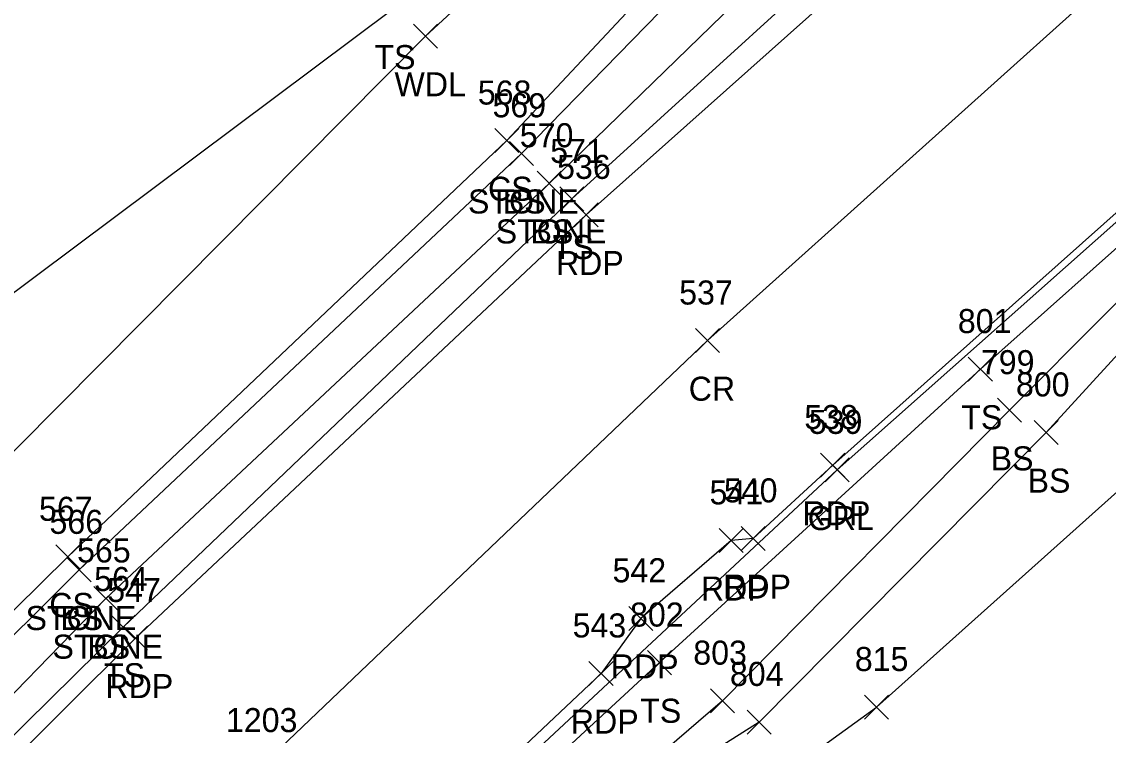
# Model space of a CAD drawing. Extents: x 1528286 to 1556263, y 492387 to 508952.
# Drawn here: x 1528382.4 to 1528472.8, y 492580.9 to 492640.2 of the extents above; entities that cross this region are included whole.
import ezdxf

# ---------------------------------------------------------------- set-up
doc = ezdxf.new("R2010")
doc.units = 0
for name, color, linetype in [('L_A', 7, 'Continuous'), ('L_I', 7, 'Continuous'), ('L_TIC', 7, 'Continuous'), ('LASF', 7, 'Continuous'), ('LAWA', 7, 'Continuous'), ('LELB', 7, 'Continuous'), ('P_A', 7, 'Continuous'), ('P_I', 7, 'Continuous'), ('P_TIC', 7, 'Continuous'), ('PET', 7, 'Continuous'), ('PRC', 7, 'Continuous'), ('R_A', 7, 'Continuous'), ('R_I', 7, 'Continuous'), ('R_TIC', 7, 'Continuous'), ('RGR', 7, 'Continuous')]:
    doc.layers.add(name, color=color, linetype=linetype)

msp = doc.modelspace()

# ---------------------------------------------------------------- linework, layer by layer
at = {"layer": 'L_TIC'}
for points in [[(1528415.012, 492638), (1528417.012, 492640)], [(1528417.012, 492638), (1528415.012, 492640)], [(1528415.012, 492638), (1528417.012, 492640)], [(1528417.012, 492638), (1528415.012, 492640)], [(1528421.772, 492629.308), (1528423.772, 492631.308)], [(1528423.772, 492629.308), (1528421.772, 492631.308)], [(1528421.772, 492629.308), (1528423.772, 492631.308)], [(1528423.772, 492629.308), (1528421.772, 492631.308)], [(1528423.002, 492628.248), (1528425.002, 492630.248)], [(1528425.002, 492628.248), (1528423.002, 492630.248)], [(1528423.002, 492628.248), (1528425.002, 492630.248)], [(1528425.002, 492628.248), (1528423.002, 492630.248)], [(1528423.002, 492628.248), (1528425.002, 492630.248)], [(1528425.002, 492628.248), (1528423.002, 492630.248)], [(1528423.002, 492628.248), (1528425.002, 492630.248)], [(1528425.002, 492628.248), (1528423.002, 492630.248)], [(1528425.307, 492625.756), (1528427.307, 492627.756)], [(1528427.307, 492625.756), (1528425.307, 492627.756)], [(1528425.307, 492625.756), (1528427.307, 492627.756)], [(1528427.307, 492625.756), (1528425.307, 492627.756)], [(1528425.307, 492625.756), (1528427.307, 492627.756)], [(1528427.307, 492625.756), (1528425.307, 492627.756)], [(1528425.307, 492625.756), (1528427.307, 492627.756)], [(1528427.307, 492625.756), (1528425.307, 492627.756)], [(1528427.184, 492624.456), (1528429.184, 492626.456)], [(1528429.184, 492624.456), (1528427.184, 492626.456)], [(1528427.184, 492624.456), (1528429.184, 492626.456)], [(1528429.184, 492624.456), (1528427.184, 492626.456)], [(1528461.188, 492610.303), (1528463.188, 492612.303)], [(1528463.188, 492610.303), (1528461.188, 492612.303)], [(1528461.188, 492610.303), (1528463.188, 492612.303)], [(1528463.188, 492610.303), (1528461.188, 492612.303)], [(1528463.603, 492606.884), (1528465.603, 492608.884)], [(1528465.603, 492606.884), (1528463.603, 492608.884)], [(1528463.603, 492606.884), (1528465.603, 492608.884)], [(1528465.603, 492606.884), (1528463.603, 492608.884)], [(1528466.677, 492605.034), (1528468.677, 492607.034)], [(1528468.677, 492605.034), (1528466.677, 492607.034)], [(1528466.677, 492605.034), (1528468.677, 492607.034)], [(1528468.677, 492605.034), (1528466.677, 492607.034)], [(1528385.249, 492594.69), (1528387.249, 492596.69)], [(1528387.249, 492594.69), (1528385.249, 492596.69)], [(1528385.249, 492594.69), (1528387.249, 492596.69)], [(1528387.249, 492594.69), (1528385.249, 492596.69)], [(1528386.178, 492593.605), (1528388.178, 492595.605)], [(1528388.178, 492593.605), (1528386.178, 492595.605)], [(1528386.178, 492593.605), (1528388.178, 492595.605)], [(1528388.178, 492593.605), (1528386.178, 492595.605)], [(1528386.178, 492593.605), (1528388.178, 492595.605)], [(1528388.178, 492593.605), (1528386.178, 492595.605)], [(1528386.178, 492593.605), (1528388.178, 492595.605)], [(1528388.178, 492593.605), (1528386.178, 492595.605)], [(1528388.417, 492591.224), (1528390.417, 492593.224)], [(1528390.417, 492591.224), (1528388.417, 492593.224)], [(1528388.417, 492591.224), (1528390.417, 492593.224)], [(1528390.417, 492591.224), (1528388.417, 492593.224)], [(1528388.417, 492591.224), (1528390.417, 492593.224)], [(1528390.417, 492591.224), (1528388.417, 492593.224)], [(1528388.417, 492591.224), (1528390.417, 492593.224)], [(1528390.417, 492591.224), (1528388.417, 492593.224)], [(1528389.84, 492588.848), (1528391.84, 492590.848)], [(1528391.84, 492588.848), (1528389.84, 492590.848)], [(1528389.84, 492588.848), (1528391.84, 492590.848)], [(1528391.84, 492588.848), (1528389.84, 492590.848)], [(1528434.473, 492585.893), (1528436.473, 492587.893)], [(1528436.473, 492585.893), (1528434.473, 492587.893)], [(1528434.473, 492585.893), (1528436.473, 492587.893)], [(1528436.473, 492585.893), (1528434.473, 492587.893)], [(1528439.739, 492582.726), (1528441.739, 492584.726)], [(1528441.739, 492582.726), (1528439.739, 492584.726)], [(1528439.739, 492582.726), (1528441.739, 492584.726)], [(1528441.739, 492582.726), (1528439.739, 492584.726)], [(1528452.537, 492582.197), (1528454.537, 492584.197)], [(1528454.537, 492582.197), (1528452.537, 492584.197)], [(1528452.537, 492582.197), (1528454.537, 492584.197)], [(1528454.537, 492582.197), (1528452.537, 492584.197)], [(1528452.537, 492582.197), (1528454.537, 492584.197)], [(1528454.537, 492582.197), (1528452.537, 492584.197)], [(1528452.537, 492582.197), (1528454.537, 492584.197)], [(1528454.537, 492582.197), (1528452.537, 492584.197)], [(1528442.787, 492580.956), (1528444.787, 492582.956)], [(1528444.787, 492580.956), (1528442.787, 492582.956)], [(1528442.787, 492580.956), (1528444.787, 492582.956)], [(1528444.787, 492580.956), (1528442.787, 492582.956)]]:
    msp.add_lwpolyline(points, dxfattribs=at)
at = {"layer": 'LASF'}
for points in [[(1528311.932, 492522.674), (1528350.128, 492557.714), (1528387.178, 492594.605), (1528424.002, 492629.248), (1528451.685, 492657.606), (1528445.371, 492665.36)], [(1528311.932, 492522.674), (1528350.128, 492557.714), (1528387.178, 492594.605), (1528424.002, 492629.248), (1528451.685, 492657.606), (1528445.371, 492665.36)], [(1528316.792, 492519.202), (1528352.681, 492554.477), (1528389.417, 492592.224), (1528426.307, 492626.756), (1528455.193, 492654.803), (1528460.128, 492658.522), (1528463.915, 492659.117), (1528453.913, 492663.497)], [(1528316.792, 492519.202), (1528352.681, 492554.477), (1528389.417, 492592.224), (1528426.307, 492626.756), (1528455.193, 492654.803), (1528460.128, 492658.522), (1528463.915, 492659.117), (1528453.913, 492663.497)]]:
    msp.add_lwpolyline(points, dxfattribs=at)
at = {"layer": 'LAWA'}
for points in [[(1528305.143, 492527.842), (1528342.933, 492565.336), (1528378.694, 492601.441), (1528416.012, 492639), (1528453.009, 492673.153), (1528472.803, 492690.435), (1528460.273, 492718.435)], [(1528305.143, 492527.842), (1528342.933, 492565.336), (1528378.694, 492601.441), (1528416.012, 492639), (1528453.009, 492673.153), (1528472.803, 492690.435), (1528460.273, 492718.435)], [(1528350.567, 492486.658), (1528374.131, 492513.994), (1528413.925, 492550.925), (1528435.091, 492569.848), (1528453.537, 492583.197), (1528487.048, 492613.162), (1528503.178, 492626.813), (1528522.579, 492648.478), (1528559.072, 492677.555), (1528579.271, 492695.125), (1528598.445, 492712.961), (1528609.007, 492715.026)], [(1528350.567, 492486.658), (1528374.131, 492513.994), (1528413.925, 492550.925), (1528435.091, 492569.848), (1528453.537, 492583.197), (1528487.048, 492613.162), (1528503.178, 492626.813), (1528522.579, 492648.478), (1528559.072, 492677.555), (1528579.271, 492695.125), (1528598.445, 492712.961), (1528609.007, 492715.026)]]:
    msp.add_lwpolyline(points, dxfattribs=at)
at = {"layer": 'LELB'}
for points in [[(1528627.535, 492747.197), (1528602.245, 492728.24), (1528590.919, 492720.18), (1528561.7, 492697.236), (1528528.44, 492669.894), (1528504.886, 492649.176), (1528486.55, 492633.133), (1528477.153, 492624.603), (1528462.188, 492611.303), (1528435.473, 492586.893), (1528420.499, 492573.078), (1528389.262, 492542.582), (1528363.671, 492517.292), (1528340.83, 492494.601)], [(1528627.535, 492747.197), (1528602.245, 492728.24), (1528590.919, 492720.18), (1528561.7, 492697.236), (1528528.44, 492669.894), (1528504.886, 492649.176), (1528486.55, 492633.133), (1528477.153, 492624.603), (1528462.188, 492611.303), (1528435.473, 492586.893), (1528420.499, 492573.078), (1528389.262, 492542.582), (1528363.671, 492517.292), (1528340.83, 492494.601)], [(1528318.253, 492517.35), (1528354.27, 492553.82), (1528390.84, 492589.848), (1528428.184, 492625.456), (1528458.023, 492652.609), (1528463.915, 492659.117), (1528457.385, 492666.329)], [(1528318.253, 492517.35), (1528354.27, 492553.82), (1528390.84, 492589.848), (1528428.184, 492625.456), (1528458.023, 492652.609), (1528463.915, 492659.117), (1528457.385, 492666.329)], [(1528311.932, 492522.674), (1528350.128, 492557.714), (1528387.178, 492594.605), (1528424.002, 492629.248), (1528451.685, 492657.606), (1528445.371, 492665.36)], [(1528311.932, 492522.674), (1528350.128, 492557.714), (1528387.178, 492594.605), (1528424.002, 492629.248), (1528451.685, 492657.606), (1528445.371, 492665.36)], [(1528441.343, 492661.958), (1528423.93, 492647.619), (1528413.351, 492641.257), (1528373.584, 492611.591), (1528326.921, 492585.971), (1528288.158, 492548.496)], [(1528441.343, 492661.958), (1528423.93, 492647.619), (1528413.351, 492641.257), (1528373.584, 492611.591), (1528326.921, 492585.971), (1528288.158, 492548.496)], [(1528310.29, 492523.886), (1528348.881, 492558.846), (1528386.249, 492595.69), (1528422.772, 492630.308), (1528448.923, 492658.21)], [(1528310.29, 492523.886), (1528348.881, 492558.846), (1528386.249, 492595.69), (1528422.772, 492630.308), (1528448.923, 492658.21)], [(1528316.792, 492519.202), (1528352.681, 492554.477), (1528389.417, 492592.224), (1528426.307, 492626.756), (1528455.193, 492654.803), (1528460.128, 492658.522)], [(1528316.792, 492519.202), (1528352.681, 492554.477), (1528389.417, 492592.224), (1528426.307, 492626.756), (1528455.193, 492654.803), (1528460.128, 492658.522)], [(1528487.933, 492626.516), (1528480.875, 492624.184), (1528464.603, 492607.884), (1528440.739, 492583.726), (1528424.526, 492569.769)], [(1528487.933, 492626.516), (1528480.875, 492624.184), (1528464.603, 492607.884), (1528440.739, 492583.726), (1528424.526, 492569.769)], [(1528489.009, 492622.822), (1528480.293, 492619.802), (1528467.677, 492606.034), (1528443.787, 492581.956), (1528424.526, 492569.769)], [(1528489.009, 492622.822), (1528480.293, 492619.802), (1528467.677, 492606.034), (1528443.787, 492581.956), (1528424.526, 492569.769)], [(1528407.988, 492556.109), (1528435.091, 492569.848), (1528453.537, 492583.197), (1528487.048, 492613.162), (1528483.53, 492620.801)], [(1528407.988, 492556.109), (1528435.091, 492569.848), (1528453.537, 492583.197), (1528487.048, 492613.162), (1528483.53, 492620.801)]]:
    msp.add_lwpolyline(points, dxfattribs=at)
at = {"layer": 'P_TIC'}
for points in [[(1528428.377, 492623.126), (1528430.377, 492625.126)], [(1528430.377, 492623.126), (1528428.377, 492625.126)], [(1528428.377, 492623.126), (1528430.377, 492625.126)], [(1528430.377, 492623.126), (1528428.377, 492625.126)], [(1528438.483, 492612.677), (1528440.483, 492614.677)], [(1528440.483, 492612.677), (1528438.483, 492614.677)], [(1528438.483, 492612.677), (1528440.483, 492614.677)], [(1528440.483, 492612.677), (1528438.483, 492614.677)], [(1528448.898, 492602.317), (1528450.898, 492604.317)], [(1528450.898, 492602.317), (1528448.898, 492604.317)], [(1528448.898, 492602.317), (1528450.898, 492604.317)], [(1528450.898, 492602.317), (1528448.898, 492604.317)], [(1528440.443, 492596.056), (1528442.443, 492598.056)], [(1528442.443, 492596.056), (1528440.443, 492598.056)], [(1528440.443, 492596.056), (1528442.443, 492598.056)], [(1528442.443, 492596.056), (1528440.443, 492598.056)], [(1528442.292, 492596.221), (1528444.292, 492598.221)], [(1528444.292, 492596.221), (1528442.292, 492598.221)], [(1528442.292, 492596.221), (1528444.292, 492598.221)], [(1528444.292, 492596.221), (1528442.292, 492598.221)], [(1528432.939, 492589.577), (1528434.939, 492591.577)], [(1528434.939, 492589.577), (1528432.939, 492591.577)], [(1528432.939, 492589.577), (1528434.939, 492591.577)], [(1528434.939, 492589.577), (1528432.939, 492591.577)], [(1528390.881, 492587.941), (1528392.881, 492589.941)], [(1528392.881, 492587.941), (1528390.881, 492589.941)], [(1528390.881, 492587.941), (1528392.881, 492589.941)], [(1528392.881, 492587.941), (1528390.881, 492589.941)], [(1528429.616, 492584.987), (1528431.616, 492586.987)], [(1528431.616, 492584.987), (1528429.616, 492586.987)], [(1528429.616, 492584.987), (1528431.616, 492586.987)], [(1528431.616, 492584.987), (1528429.616, 492586.987)]]:
    msp.add_lwpolyline(points, dxfattribs=at)
at = {"layer": 'PET'}
for points in [[(1528560.517, 492699.264), (1528557.469, 492699.118), (1528553.458, 492694.773), (1528549.097, 492692.715), (1528547.05, 492688.292), (1528537.757, 492682.515), (1528535.94, 492680.254), (1528535.911, 492679.061), (1528519.42, 492665.123), (1528485.647, 492635.106), (1528449.898, 492603.317), (1528443.292, 492597.221), (1528441.443, 492597.056), (1528433.939, 492590.577), (1528430.616, 492585.987), (1528412.089, 492568.516), (1528375.77, 492531.986), (1528339.078, 492496.271)], [(1528560.517, 492699.264), (1528557.469, 492699.118), (1528553.458, 492694.773), (1528549.097, 492692.715), (1528547.05, 492688.292), (1528537.757, 492682.515), (1528535.94, 492680.254), (1528535.911, 492679.061), (1528519.42, 492665.123), (1528485.647, 492635.106), (1528449.898, 492603.317), (1528443.292, 492597.221), (1528441.443, 492597.056), (1528433.939, 492590.577), (1528430.616, 492585.987), (1528412.089, 492568.516), (1528375.77, 492531.986), (1528339.078, 492496.271)], [(1528466.456, 492657.166), (1528429.377, 492624.126), (1528391.881, 492588.941), (1528355.416, 492552.695), (1528318.996, 492516.325)], [(1528466.456, 492657.166), (1528429.377, 492624.126), (1528391.881, 492588.941), (1528355.416, 492552.695), (1528318.996, 492516.325)]]:
    msp.add_lwpolyline(points, dxfattribs=at)
at = {"layer": 'PRC'}
for points in [[(1528475.829, 492646.31), (1528439.483, 492613.677)], [(1528475.829, 492646.31), (1528439.483, 492613.677)], [(1528402.171, 492578.118), (1528439.483, 492613.677)], [(1528402.171, 492578.118), (1528439.483, 492613.677)]]:
    msp.add_lwpolyline(points, dxfattribs=at)
at = {"layer": 'R_TIC'}
for points in [[(1528449.283, 492601.919), (1528451.283, 492603.919)], [(1528451.283, 492601.919), (1528449.283, 492603.919)], [(1528449.283, 492601.919), (1528451.283, 492603.919)], [(1528451.283, 492601.919), (1528449.283, 492603.919)]]:
    msp.add_lwpolyline(points, dxfattribs=at)
at = {"layer": 'RGR'}
msp.add_lwpolyline([(1528631.557, 492751.518), (1528593.228, 492723.7), (1528555.254, 492694.171), (1528520.288, 492664.562), (1528486.051, 492634.677), (1528450.283, 492602.919), (1528412.918, 492568.153), (1528376.626, 492531.198), (1528339.769, 492495.46)], dxfattribs=at)
msp.add_lwpolyline([(1528631.557, 492751.518), (1528593.228, 492723.7), (1528555.254, 492694.171), (1528520.288, 492664.562), (1528486.051, 492634.677), (1528450.283, 492602.919), (1528412.918, 492568.153), (1528376.626, 492531.198), (1528339.769, 492495.46)], dxfattribs=at)

# ---------------------------------------------------------------- texts
at = {"layer": 'L_A'}
for s, p in [('TS', (1528411.76, 492636.257)), ('TS', (1528411.76, 492636.257)), ('WDL', (1528413.43, 492634)), ('WDL', (1528413.43, 492634)), ('CS', (1528421.213, 492625.308)), ('CS', (1528421.213, 492625.308)), ('STONE', (1528419.545, 492624.248)), ('STONE', (1528419.545, 492624.248)), ('BS', (1528422.443, 492624.248)), ('BS', (1528422.443, 492624.248)), ('STONE', (1528421.851, 492621.756)), ('STONE', (1528421.851, 492621.756)), ('BS', (1528424.748, 492621.756)), ('BS', (1528424.748, 492621.756)), ('TS', (1528426.593, 492620.456)), ('TS', (1528426.593, 492620.456)), ('TS', (1528460.598, 492606.303)), ('TS', (1528460.598, 492606.303)), ('BS', (1528463.044, 492602.884)), ('BS', (1528463.044, 492602.884)), ('BS', (1528466.118, 492601.034)), ('BS', (1528466.118, 492601.034)), ('CS', (1528384.69, 492590.69)), ('CS', (1528384.69, 492590.69)), ('STONE', (1528382.721, 492589.605)), ('STONE', (1528382.721, 492589.605)), ('BS', (1528385.618, 492589.605)), ('BS', (1528385.618, 492589.605)), ('STONE', (1528384.96, 492587.224)), ('STONE', (1528384.96, 492587.224)), ('BS', (1528387.858, 492587.224)), ('BS', (1528387.858, 492587.224)), ('TS', (1528389.249, 492584.848)), ('TS', (1528389.249, 492584.848)), ('TS', (1528433.882, 492581.893)), ('TS', (1528433.882, 492581.893))]:
    msp.add_text(s, height=2, dxfattribs=at).set_placement(p)
at = {"layer": 'L_I'}
for s, p in [('568', (1528420.362, 492633.308)), ('568', (1528420.362, 492633.308)), ('569', (1528421.585, 492632.248)), ('569', (1528421.585, 492632.248)), ('569', (1528421.585, 492632.248)), ('569', (1528421.585, 492632.248)), ('570', (1528423.858, 492629.756)), ('570', (1528423.858, 492629.756)), ('570', (1528423.858, 492629.756)), ('570', (1528423.858, 492629.756)), ('571', (1528426.388, 492628.456)), ('571', (1528426.388, 492628.456)), ('801', (1528460.314, 492614.303)), ('801', (1528460.314, 492614.303)), ('799', (1528462.233, 492610.884)), ('799', (1528462.233, 492610.884)), ('800', (1528465.149, 492609.034)), ('800', (1528465.149, 492609.034)), ('567', (1528383.839, 492598.69)), ('567', (1528383.839, 492598.69)), ('566', (1528384.713, 492597.605)), ('566', (1528384.713, 492597.605)), ('566', (1528384.713, 492597.605)), ('566', (1528384.713, 492597.605)), ('565', (1528387.007, 492595.224)), ('565', (1528387.007, 492595.224)), ('565', (1528387.007, 492595.224)), ('565', (1528387.007, 492595.224)), ('564', (1528388.43, 492592.848)), ('564', (1528388.43, 492592.848)), ('802', (1528433.032, 492589.893)), ('802', (1528433.032, 492589.893)), ('803', (1528438.298, 492586.726)), ('803', (1528438.298, 492586.726)), ('815', (1528451.741, 492586.197)), ('815', (1528451.741, 492586.197)), ('815', (1528451.741, 492586.197)), ('815', (1528451.741, 492586.197)), ('804', (1528441.347, 492584.956)), ('804', (1528441.347, 492584.956))]:
    msp.add_text(s, height=2, dxfattribs=at).set_placement(p)
at = {"layer": 'P_A'}
for s, p in [('RDP', (1528426.865, 492619.126)), ('RDP', (1528426.865, 492619.126)), ('CR', (1528437.917, 492608.677)), ('CR', (1528437.917, 492608.677)), ('RDP', (1528447.387, 492598.317)), ('RDP', (1528447.387, 492598.317)), ('RDP', (1528438.931, 492592.056)), ('RDP', (1528438.931, 492592.056)), ('RDP', (1528440.78, 492592.221)), ('RDP', (1528440.78, 492592.221)), ('RDP', (1528431.427, 492585.577)), ('RDP', (1528431.427, 492585.577)), ('RDP', (1528389.369, 492583.941)), ('RDP', (1528389.369, 492583.941)), ('RDP', (1528428.105, 492580.987)), ('RDP', (1528428.105, 492580.987))]:
    msp.add_text(s, height=2, dxfattribs=at).set_placement(p)
at = {"layer": 'P_I'}
for s, p in [('536', (1528426.96, 492627.126)), ('536', (1528426.96, 492627.126)), ('537', (1528437.121, 492616.677)), ('537', (1528437.121, 492616.677)), ('538', (1528447.536, 492606.317)), ('538', (1528447.536, 492606.317)), ('541', (1528439.647, 492600.056)), ('541', (1528439.647, 492600.056)), ('540', (1528440.843, 492600.221)), ('540', (1528440.843, 492600.221)), ('542', (1528431.576, 492593.577)), ('542', (1528431.576, 492593.577)), ('547', (1528389.519, 492591.941)), ('547', (1528389.519, 492591.941)), ('543', (1528428.254, 492588.987)), ('543', (1528428.254, 492588.987)), ('1203', (1528399.399, 492581.118)), ('1203', (1528399.399, 492581.118)), ('1203', (1528399.399, 492581.118)), ('1203', (1528399.399, 492581.118))]:
    msp.add_text(s, height=2, dxfattribs=at).set_placement(p)
at = {"layer": 'R_A'}
msp.add_text('GRL', height=2, dxfattribs=at).set_placement((1528447.826, 492597.919))
msp.add_text('GRL', height=2, dxfattribs=at).set_placement((1528447.826, 492597.919))
at = {"layer": 'R_I'}
msp.add_text('539', height=2, dxfattribs=at).set_placement((1528447.913, 492605.919))
msp.add_text('539', height=2, dxfattribs=at).set_placement((1528447.913, 492605.919))

doc.saveas('drawing.dxf')
